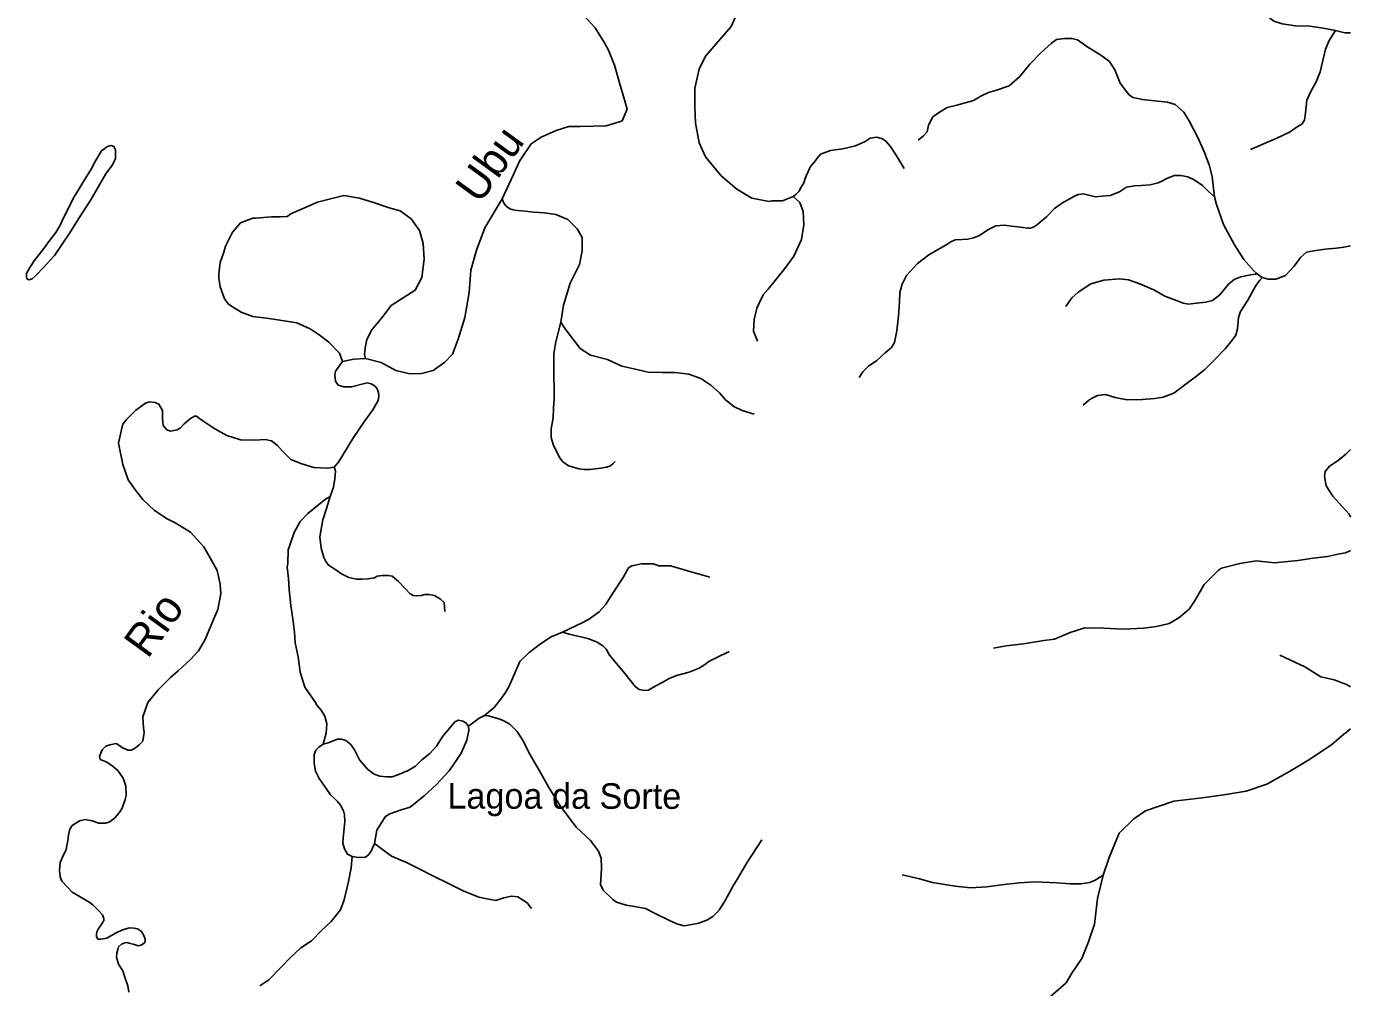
# Model space of a CAD drawing. Extents: x 436.3 to 500.4, y 8231 to 8286.4.
# Drawn here: x 491.72 to 500, y 8239.13 to 8245.15 of the extents above; entities that cross this region are included whole.
import ezdxf
from ezdxf.enums import TextEntityAlignment as Align

# ---------------------------------------------------------------- set-up
doc = ezdxf.new("R2010")
doc.units = 0
doc.header["$LTSCALE"] = 0.08
doc.linetypes.add('LONG_DASHED', pattern=[7.5, 6, -1.5])
doc.layers.add('2', color=7, linetype='Continuous', lineweight=25)
doc.layers.add('9', color=7, linetype='LONG_DASHED', lineweight=25)
doc.layers.add('61', color=7, linetype='Continuous')

msp = doc.modelspace()

# ---------------------------------------------------------------- linework, layer by layer
at = {"layer": '2'}
msp.add_lwpolyline([(492.1214, 8244.2542), (492.0745, 8244.1764), (492.0419, 8244.125), (492.0114, 8244.076), (491.9787, 8244.0059), (491.946, 8243.9452), (491.9249, 8243.9007), (491.9016, 8243.8586), (491.8643, 8243.8095), (491.8199, 8243.7486), (491.7661, 8243.6808), (491.7358, 8243.634), (491.7172, 8243.6012), (491.7172, 8243.5802), (491.7195, 8243.5684), (491.7336, 8243.5614), (491.7522, 8243.5684), (491.7756, 8243.5894), (491.8246, 8243.6385), (491.8923, 8243.7135), (491.988, 8243.8561), (492.0419, 8243.9426), (492.119, 8244.0617), (492.1681, 8244.1457), (492.2126, 8244.2251), (492.2547, 8244.2819), (492.2735, 8244.3215), (492.2736, 8244.3752), (492.2642, 8244.3963), (492.2478, 8244.4034), (492.2244, 8244.3965), (492.187, 8244.3685), (492.1472, 8244.3032)], close=True, dxfattribs=at)
for points in [[(493.574, 8240.6561), (493.6045, 8240.6636), (493.6325, 8240.6737), (493.6631, 8240.6863), (493.6886, 8240.6862), (493.714, 8240.6784), (493.7472, 8240.6528), (493.77, 8240.6196), (493.8012, 8240.558), (493.8495, 8240.4992), (493.8929, 8240.4685), (493.9285, 8240.4557), (493.9693, 8240.4504), (494.0049, 8240.4502), (494.0406, 8240.4628), (494.1043, 8240.4906), (494.1502, 8240.5184), (494.191, 8240.5564), (494.2395, 8240.5969), (494.2828, 8240.6426), (494.3211, 8240.7061), (494.367, 8240.7594), (494.3977, 8240.7949), (494.4206, 8240.805), (494.446, 8240.7998), (494.4664, 8240.7895), (494.4817, 8240.7691)], [(494.4817, 8240.7691), (494.4843, 8240.741), (494.4714, 8240.68), (494.4357, 8240.5986), (494.4076, 8240.5555), (494.3617, 8240.4895), (494.2826, 8240.4033), (494.206, 8240.3323), (494.1168, 8240.2615), (494.0601, 8240.2453), (493.9912, 8240.2202), (493.9632, 8240.2025), (493.9351, 8240.1619), (493.9096, 8240.1162), (493.8942, 8240.0341)], [(493.754, 8239.9516), (493.726, 8239.9669), (493.7057, 8240.0001), (493.6955, 8240.0357), (493.6981, 8240.0687), (493.7033, 8240.1094), (493.7084, 8240.1719), (493.706, 8240.2127), (493.7009, 8240.2381), (493.6806, 8240.2738), (493.6627, 8240.2967), (493.6373, 8240.3223), (493.6195, 8240.3377), (493.5915, 8240.3784), (493.5483, 8240.4398), (493.5254, 8240.4856), (493.5178, 8240.534), (493.5179, 8240.5901), (493.5281, 8240.6181), (493.5459, 8240.6358), (493.574, 8240.6561)], [(493.8942, 8240.0341), (493.8763, 8239.9893), (493.8584, 8239.9639), (493.838, 8239.9487), (493.7922, 8239.9464), (493.754, 8239.9516)]]:
    msp.add_lwpolyline(points, dxfattribs=at)
at = {"layer": '9'}
for points in [[(498.815, 8245.6547), (498.9221, 8245.6748), (498.9954, 8245.6637), (499.08, 8245.6161), (499.1138, 8245.5766), (499.1391, 8245.5542), (499.1391, 8245.5316), (499.1307, 8245.492), (499.1082, 8245.4412), (499.0856, 8245.4073), (499.0771, 8245.3762), (499.0884, 8245.3311), (499.1222, 8245.3087), (499.204, 8245.2863), (499.2971, 8245.2641), (499.438, 8245.2419), (499.4719, 8245.2195), (499.4944, 8245.1998), (499.5197, 8245.1802), (499.5734, 8245.1634), (499.6551, 8245.1524), (499.7453, 8245.1499), (499.8299, 8245.136), (499.906, 8245.1222)], [(496.5133, 8244.0823), (496.4978, 8244.0772), (496.4462, 8244.0565), (496.379, 8244.0566), (496.3633, 8244.0514), (496.2548, 8244.0723), (496.1619, 8244.1292), (496.0637, 8244.212), (495.9655, 8244.331), (495.9243, 8244.4189), (495.9032, 8244.5444), (495.8981, 8244.6425), (495.8983, 8244.7613), (495.9243, 8244.88), (495.9657, 8244.9625), (496.0589, 8245.0708), (496.1262, 8245.1481), (496.1624, 8245.2306), (496.1602, 8245.2649), (496.1571, 8245.3194)], [(495.2025, 8245.2173), (495.2753, 8245.1391), (495.3326, 8245.0452), (495.3586, 8244.9984), (495.395, 8244.9046), (495.4261, 8244.7952), (495.4585, 8244.6876), (495.4689, 8244.6512), (495.4742, 8244.6303), (495.4428, 8244.5576), (495.4324, 8244.5524), (495.3437, 8244.5266), (495.1821, 8244.522), (495.1091, 8244.5222), (495.0309, 8244.4965), (494.937, 8244.4553), (494.8744, 8244.4138), (494.8013, 8244.3048), (494.7647, 8244.2218), (494.6927, 8244.0679)], [(499.3735, 8244.3769), (499.4805, 8244.4229), (499.534, 8244.4457), (499.6187, 8244.4854), (499.6666, 8244.5195), (499.6948, 8244.5365), (499.7117, 8244.5619), (499.7174, 8244.6071), (499.7259, 8244.686), (499.7512, 8244.7396), (499.785, 8244.8018), (499.8104, 8244.864), (499.8274, 8244.9346), (499.8442, 8245.0051), (499.8668, 8245.0588), (499.8865, 8245.0927), (499.906, 8245.1222)], [(499.906, 8245.1222), (499.9653, 8245.1083), (500, 8245.1078)], [(497.2961, 8244.4365), (497.3284, 8244.4622), (497.351, 8244.4881), (497.3607, 8244.53), (497.3865, 8244.5815), (497.4285, 8244.6106), (497.4769, 8244.6396), (497.5381, 8244.6558), (497.5897, 8244.6688), (497.6413, 8244.685), (497.6865, 8244.7108), (497.7349, 8244.7335), (497.78, 8244.7464), (497.8638, 8244.7755), (497.9315, 8244.8337), (497.9929, 8244.9111), (498.0639, 8244.9854), (498.1283, 8245.0404), (498.1605, 8245.0663), (498.2121, 8245.0728), (498.2573, 8245.0729), (498.2926, 8245.0634), (498.3507, 8245.0216), (498.4377, 8244.967), (498.4924, 8244.9285), (498.5247, 8244.877), (498.56, 8244.7932), (498.5901, 8244.7512), (498.6127, 8244.7222), (498.6384, 8244.703), (498.6996, 8244.6903), (498.7545, 8244.684), (498.8544, 8244.6746), (498.9026, 8244.6586), (498.9575, 8244.6105), (498.9928, 8244.5525), (499.0444, 8244.4527), (499.0863, 8244.3594), (499.1153, 8244.2821), (499.1347, 8244.208), (499.1499, 8244.0818)], [(497.2074, 8244.2582), (497.1712, 8244.3202), (497.1454, 8244.3615), (497.1196, 8244.3976), (497.0937, 8244.4286), (497.0731, 8244.4441), (497.037, 8244.4544), (496.9956, 8244.4492), (496.9645, 8244.4285), (496.9032, 8244.4008), (496.8233, 8244.3815), (496.7474, 8244.3718), (496.6841, 8244.3477), (496.6678, 8244.3279), (496.6461, 8244.3008), (496.6226, 8244.2701), (496.5972, 8244.2178), (496.5881, 8244.1961), (496.5809, 8244.169), (496.5592, 8244.1347), (496.5501, 8244.1167), (496.5302, 8244.0968), (496.5133, 8244.0823)], [(496.9264, 8242.9495), (496.9486, 8242.9864), (496.9855, 8243.0209), (497.0373, 8243.0577), (497.0889, 8243.1045), (497.1283, 8243.1389), (497.1481, 8243.1685), (497.1628, 8243.2422), (497.1728, 8243.3357), (497.178, 8243.4249), (497.1804, 8243.4814), (497.1953, 8243.5356), (497.2223, 8243.5896), (497.2913, 8243.6634), (497.3626, 8243.7176), (497.4413, 8243.7643), (497.4741, 8243.7821), (497.4987, 8243.7994), (497.5258, 8243.8117), (497.57, 8243.8143), (497.6069, 8243.8167), (497.6414, 8243.8242), (497.6758, 8243.8365), (497.7348, 8243.8759), (497.7815, 8243.9006), (497.8332, 8243.9031), (497.8971, 8243.8959), (497.952, 8243.889), (497.979, 8243.8841), (497.9962, 8243.8842), (498.011, 8243.8891), (498.0331, 8243.9014), (498.0972, 8243.9556), (498.1488, 8244.0073), (498.198, 8244.0444), (498.2724, 8244.0844), (498.297, 8244.0966), (498.3289, 8244.0992), (498.3633, 8244.0919), (498.4051, 8244.0822), (498.4445, 8244.0848), (498.4961, 8244.0898), (498.5551, 8244.1121), (498.5993, 8244.1417), (498.6485, 8244.1491), (498.6903, 8244.1518), (498.7469, 8244.1568), (498.7961, 8244.1693), (498.8206, 8244.1791), (498.8501, 8244.1964), (498.8968, 8244.2138), (498.9386, 8244.2139), (498.9829, 8244.2066), (499.0221, 8244.1871), (499.0738, 8244.1529), (499.1082, 8244.1186), (499.1499, 8244.0818)], [(493.838, 8243.069), (493.8313, 8243.0949), (493.8351, 8243.1364), (493.8465, 8243.1892), (493.8767, 8243.2495), (493.941, 8243.3248), (493.9977, 8243.4001), (494.0733, 8243.4489), (494.1489, 8243.4976), (494.1905, 8243.5768), (494.2057, 8243.6901), (494.1982, 8243.7884), (494.1756, 8243.8715), (494.1227, 8243.9435), (494.0547, 8243.993), (493.9867, 8244.0121), (493.8884, 8244.0466), (493.8015, 8244.0735), (493.7033, 8244.0891), (493.6276, 8244.0706), (493.537, 8244.0484), (493.3706, 8243.9738), (493.3479, 8243.9588), (493.3064, 8243.9552), (493.2497, 8243.9555), (493.1515, 8243.9485), (493.1326, 8243.9486), (493.057, 8243.9187), (493.0079, 8243.8624), (493.0003, 8243.8473), (492.9625, 8243.7719), (492.9512, 8243.7342), (492.9285, 8243.6701), (492.921, 8243.5983), (492.921, 8243.5719), (492.9285, 8243.5189), (492.955, 8243.4431), (492.9814, 8243.4091), (493.0154, 8243.3862), (493.0607, 8243.3595), (493.1325, 8243.3327), (493.2194, 8243.321), (493.3025, 8243.3093), (493.4082, 8243.2936), (493.4913, 8243.2554), (493.548, 8243.2173), (493.6084, 8243.1717), (493.6745, 8243.103), (493.6944, 8243.0515)], [(494.6927, 8244.0679), (494.5852, 8243.8882), (494.5329, 8243.7479), (494.4963, 8243.6231), (494.4858, 8243.4824), (494.4597, 8243.3262), (494.4179, 8243.191), (494.3814, 8243.0973), (494.3344, 8243.0454), (494.2615, 8242.9936), (494.1891, 8242.9755), (494.1156, 8242.9735), (494.0282, 8242.9935), (493.9364, 8243.0446), (493.838, 8243.069)], [(495.06, 8243.2976), (495.0759, 8243.4036), (495.1186, 8243.5413), (495.177, 8243.6578), (495.193, 8243.7425), (495.1931, 8243.8273), (495.1613, 8243.8805), (495.1029, 8243.9389), (495.0292, 8243.9696), (494.958, 8243.9809), (494.8917, 8243.9861), (494.8364, 8243.9924), (494.7884, 8243.9963), (494.7626, 8244.0001), (494.7418, 8244.0063), (494.7172, 8244.0236), (494.7025, 8244.0421), (494.6927, 8244.0679)], [(496.2902, 8243.1783), (496.2644, 8243.2404), (496.2696, 8243.3127), (496.2852, 8243.3851), (496.3007, 8243.4161), (496.3267, 8243.4677), (496.3577, 8243.5038), (496.4613, 8243.6329), (496.5181, 8243.7104), (496.5647, 8243.8136), (496.5803, 8243.9067), (496.5753, 8243.9893), (496.5547, 8244.0461), (496.5133, 8244.0823)], [(499.1499, 8244.0818), (499.1609, 8244.0329), (499.2061, 8243.9073), (499.2737, 8243.7818), (499.3318, 8243.6885), (499.3962, 8243.6178), (499.4147, 8243.6005)], [(499.4489, 8243.5765), (499.4847, 8243.5666), (499.5318, 8243.5654), (499.5929, 8243.5884), (499.6477, 8243.6466), (499.6864, 8243.7016), (499.7251, 8243.7339), (499.7702, 8243.7438), (499.8412, 8243.7536), (499.9121, 8243.7604), (499.9572, 8243.7669), (500, 8243.7745)], [(498.2185, 8243.3938), (498.2572, 8243.4488), (498.2959, 8243.4843), (498.3765, 8243.5361), (498.4571, 8243.5588), (498.5539, 8243.5688), (498.6119, 8243.5624), (498.6829, 8243.5369), (498.7699, 8243.4984), (498.8376, 8243.4599), (498.9214, 8243.4279), (498.9536, 8243.4151), (498.9859, 8243.4088), (499.0375, 8243.4153), (499.0955, 8243.422), (499.1375, 8243.4318), (499.1826, 8243.4674), (499.2375, 8243.5352), (499.2729, 8243.5644), (499.3148, 8243.5806), (499.3631, 8243.5905), (499.3888, 8243.5943), (499.4066, 8243.5976), (499.4147, 8243.6005)], [(498.3279, 8242.7768), (498.3602, 8242.8059), (498.3795, 8242.8189), (498.4182, 8242.8384), (498.4666, 8242.8449), (498.5279, 8242.8258), (498.602, 8242.8099), (498.6988, 8242.8133), (498.7762, 8242.82), (498.8278, 8242.8266), (498.8955, 8242.8525), (498.9891, 8242.9237), (499.0278, 8242.9529), (499.0891, 8243.0014), (499.1471, 8243.0596), (499.2148, 8243.1307), (499.2605, 8243.1836), (499.2831, 8243.216), (499.2927, 8243.2547), (499.2992, 8243.3256), (499.3121, 8243.3644), (499.3572, 8243.4354), (499.4056, 8243.5226), (499.4204, 8243.543), (499.4337, 8243.5587), (499.4434, 8243.5702), (499.4489, 8243.5765)], [(499.4147, 8243.6005), (499.4259, 8243.59), (499.4429, 8243.5782), (499.4489, 8243.5765)], [(495.4, 8242.4243), (495.3851, 8242.4095), (495.3702, 8242.3972), (495.3455, 8242.3898), (495.3108, 8242.3825), (495.244, 8242.3753), (495.2069, 8242.3755), (495.1747, 8242.378), (495.1079, 8242.398), (495.0732, 8242.4229), (495.0534, 8242.4477), (495.0139, 8242.5247), (494.9991, 8242.5742), (494.9991, 8242.6287), (495.0116, 8242.6979), (495.014, 8242.7598), (495.0191, 8242.8143), (495.0191, 8242.8786), (495.0167, 8242.953), (495.0167, 8243.0148), (495.0168, 8243.1014), (495.0288, 8243.1742), (495.06, 8243.2976)], [(496.269, 8242.7217), (496.1947, 8242.7431), (496.1417, 8242.7697), (496.0886, 8242.8122), (496.0516, 8242.8546), (495.9986, 8242.9025), (495.935, 8242.945), (495.8607, 8242.9717), (495.7759, 8242.9825), (495.6963, 8242.9827), (495.606, 8242.983), (495.5159, 8243.0044), (495.4416, 8243.0206), (495.3515, 8243.0632), (495.2454, 8243.0901), (495.1819, 8243.1328), (495.0864, 8243.2552), (495.06, 8243.2976)], [(493.6944, 8243.0515), (493.6506, 8242.9907), (493.6454, 8242.9646), (493.6506, 8242.9281), (493.6663, 8242.9019), (493.7028, 8242.8913), (493.7496, 8242.8911), (493.8486, 8242.9167), (493.8742, 8242.9114), (493.898, 8242.8961), (493.911, 8242.8787), (493.9195, 8242.8569), (493.9217, 8242.8332), (493.9174, 8242.8072), (493.8849, 8242.7488), (493.833, 8242.6799), (493.7637, 8242.574), (493.6988, 8242.4682), (493.6685, 8242.4206), (493.6413, 8242.3893)], [(493.838, 8243.069), (493.7655, 8243.066), (493.6944, 8243.0515)], [(493.6413, 8242.3893), (493.5995, 8242.3819), (493.5157, 8242.3861), (493.4396, 8242.4093), (493.371, 8242.4363), (493.3178, 8242.4899), (493.2873, 8242.5244), (493.2492, 8242.555), (493.2111, 8242.5628), (493.1465, 8242.5592), (493.0552, 8242.5596), (492.9713, 8242.5867), (492.8953, 8242.6289), (492.8268, 8242.675), (492.7997, 8242.6941), (492.7807, 8242.7094), (492.7693, 8242.7094), (492.7427, 8242.6943), (492.7046, 8242.6601), (492.678, 8242.6335), (492.659, 8242.6221), (492.64, 8242.6184), (492.6171, 8242.6146), (492.5943, 8242.6223), (492.5715, 8242.6491), (492.5677, 8242.6911), (492.5676, 8242.7445), (492.5447, 8242.7827), (492.522, 8242.7942), (492.4877, 8242.7982), (492.4611, 8242.7906), (492.4003, 8242.7451), (492.3427, 8242.6878), (492.3198, 8242.6573), (492.3085, 8242.6154), (492.2933, 8242.5391), (492.32, 8242.4055), (492.3543, 8242.3101), (492.4, 8242.2451), (492.4456, 8242.1877), (492.5179, 8242.1188), (492.5978, 8242.0651), (492.648, 8242.0399), (492.7431, 8241.9825), (492.8268, 8241.8906), (492.8762, 8241.8028), (492.9105, 8241.7416), (492.9295, 8241.6577), (492.9333, 8241.5967), (492.9142, 8241.4977), (492.88, 8241.4216), (492.8344, 8241.3113), (492.7925, 8241.2391), (492.7431, 8241.1859), (492.667, 8241.1137), (492.6176, 8241.0719), (492.5416, 8240.9959), (492.4769, 8240.9161), (492.4457, 8240.8268), (492.4495, 8240.7582), (492.4532, 8240.7278), (492.4456, 8240.6745), (492.4228, 8240.6517), (492.4, 8240.6328), (492.3734, 8240.6175), (492.3505, 8240.6176), (492.3202, 8240.633), (492.2784, 8240.6597), (492.2394, 8240.6512), (492.2128, 8240.6437), (492.19, 8240.6208), (492.1749, 8240.579), (492.1786, 8240.5599), (492.2166, 8240.5447), (492.2507, 8240.5218), (492.2887, 8240.4913), (492.3229, 8240.4418), (492.3381, 8240.3922), (492.3418, 8240.3351), (492.3341, 8240.3086), (492.3151, 8240.2553), (492.2962, 8240.225), (492.2695, 8240.1947), (492.2466, 8240.1756), (492.2315, 8240.1681), (492.2124, 8240.1605), (492.1706, 8240.1606), (492.1289, 8240.1758), (492.0833, 8240.1835), (492.0491, 8240.1759), (492.0035, 8240.1456), (491.9883, 8240.1229), (491.9807, 8240.0886), (491.9769, 8240.0506), (491.9693, 8240.0202)], [(500, 8242.0752), (499.9916, 8242.0941), (499.9503, 8242.1415), (499.89, 8242.2079), (499.8479, 8242.2715), (499.8364, 8242.3304), (499.8424, 8242.3631), (499.8678, 8242.3949), (499.9217, 8242.43), (499.9712, 8242.4715), (500, 8242.4988)], [(493.6174, 8242.2056), (493.6387, 8242.2644), (493.6471, 8242.3169), (493.6513, 8242.3632), (493.6413, 8242.3893)], [(493.574, 8240.6561), (493.5919, 8240.7247), (493.5962, 8240.7835), (493.5836, 8240.8297), (493.5647, 8240.8613), (493.529, 8240.9056), (493.529, 8240.9098), (493.4578, 8241.013), (493.4285, 8241.1055), (493.4174, 8241.2029), (493.3986, 8241.2891), (493.3944, 8241.3564), (493.384, 8241.4405), (493.3714, 8241.5226), (493.3609, 8241.6205), (493.3568, 8241.6921), (493.3484, 8241.7635), (493.3526, 8241.7866), (493.3547, 8241.8708), (493.3631, 8241.8939), (493.3925, 8241.98), (493.4283, 8242.0487), (493.4767, 8242.099), (493.5439, 8242.1533), (493.5879, 8242.1889), (493.6174, 8242.2056)], [(494.3347, 8241.4866), (494.3292, 8241.5413), (494.3075, 8241.5632), (494.2692, 8241.5852), (494.2356, 8241.5916), (494.2083, 8241.5917), (494.1852, 8241.5855), (494.16, 8241.5835), (494.1369, 8241.5857), (494.118, 8241.5963), (494.0865, 8241.6301), (494.0445, 8241.6744), (494.0046, 8241.7061), (493.9815, 8241.7104), (493.9437, 8241.7106), (493.9101, 8241.7066), (493.8933, 8241.6961), (493.8555, 8241.69), (493.8177, 8241.688), (493.782, 8241.6882), (493.7337, 8241.6989), (493.6832, 8241.7244), (493.6518, 8241.7476), (493.6056, 8241.7751), (493.5902, 8241.799), (493.5776, 8241.8243), (493.5608, 8241.8832), (493.5524, 8241.9527), (493.5713, 8242.0598), (493.5944, 8242.1312), (493.6174, 8242.2056)], [(497.7672, 8241.2553), (497.8466, 8241.2714), (497.9546, 8241.2844), (498.0816, 8241.3037), (498.1484, 8241.3134), (498.2468, 8241.3549), (498.3389, 8241.3837), (498.4564, 8241.3809), (498.5803, 8241.375), (498.7041, 8241.3817), (498.7866, 8241.3914), (498.8661, 8241.4107), (498.9264, 8241.4457), (498.9899, 8241.4998), (499.0281, 8241.557), (499.0852, 8241.6555), (499.1741, 8241.7445), (499.1931, 8241.7573), (499.3075, 8241.7862), (499.4105, 8241.8031), (499.5248, 8241.7908), (499.6708, 8241.804), (499.7661, 8241.8201), (499.855, 8241.8299), (499.9311, 8241.846), (499.9691, 8241.8537), (499.9866, 8241.862), (500, 8241.8674)], [(495.9916, 8241.6998), (495.9344, 8241.7168), (495.8672, 8241.737), (495.7967, 8241.7574), (495.7463, 8241.7709), (495.6723, 8241.7711), (495.6387, 8241.7846), (495.5648, 8241.7847), (495.5043, 8241.7715), (495.484, 8241.7581), (495.4504, 8241.6976), (495.3898, 8241.6071), (495.3596, 8241.5601), (495.3393, 8241.5266), (495.299, 8241.483), (495.2385, 8241.4396), (495.1982, 8241.4162), (495.07, 8241.3556)], [(495.07, 8241.3556), (494.9991, 8241.3263), (494.9319, 8241.2829), (494.8612, 8241.2293), (494.8041, 8241.1725), (494.7638, 8241.0819), (494.7368, 8241.0183), (494.7133, 8240.9781), (494.683, 8240.9345), (494.6426, 8240.8843), (494.5829, 8240.8359)], [(496.1123, 8241.2348), (496.0363, 8241.197), (495.9857, 8241.1738), (495.9582, 8241.1528), (495.9244, 8241.1318), (495.8632, 8241.1066), (495.7914, 8241.0877), (495.7428, 8241.0688), (495.6943, 8241.0415), (495.6542, 8241.0205), (495.6288, 8241.0058), (495.6077, 8240.9932), (495.5803, 8240.9912), (495.5508, 8240.9976), (495.5254, 8241.0167), (495.4622, 8241.0948), (495.3653, 8241.2133), (495.3442, 8241.2492), (495.3231, 8241.2703), (495.2873, 8241.2936), (495.2282, 8241.317), (495.1671, 8241.332), (495.1122, 8241.3448), (495.07, 8241.3556)], [(499.5568, 8241.2128), (499.7152, 8241.1385), (499.8152, 8241.0779), (499.8986, 8241.0587), (499.9755, 8241.0292), (500, 8241.0152)], [(494.5829, 8240.8359), (494.5485, 8240.8176), (494.4817, 8240.7691)], [(496.3169, 8240.0576), (496.2226, 8239.9136), (496.1654, 8239.8132), (496.1384, 8239.7697), (496.0879, 8239.6761), (496.0508, 8239.616), (496.0105, 8239.5759), (495.9768, 8239.5559), (495.923, 8239.5359), (495.8793, 8239.5259), (495.8322, 8239.5193), (495.7919, 8239.5294), (495.7448, 8239.5495), (495.6508, 8239.5965), (495.5903, 8239.6268), (495.5198, 8239.6404), (495.4694, 8239.6472), (495.4089, 8239.6674), (495.3854, 8239.6842), (495.3249, 8239.7413), (495.3082, 8239.7781), (495.315, 8239.8752), (495.315, 8239.8819), (495.3117, 8239.9422), (495.2949, 8239.9857), (495.2446, 8240.0529), (495.1573, 8240.1336), (495.0554, 8240.2697), (494.985, 8240.3841), (494.9347, 8240.4748), (494.8676, 8240.5891), (494.8206, 8240.6832), (494.787, 8240.7338), (494.7401, 8240.7809), (494.6997, 8240.8046), (494.673, 8240.8147), (494.6058, 8240.8318), (494.5829, 8240.8359)], [(498.453, 8239.8364), (498.49, 8239.9457), (498.5528, 8240.0974), (498.6446, 8240.1891), (498.7181, 8240.2381), (498.8955, 8240.2997), (499.0728, 8240.3186), (499.2074, 8240.3373), (499.3482, 8240.3621), (499.4766, 8240.4053), (499.6173, 8240.485), (499.7335, 8240.5524), (499.8802, 8240.6506), (499.9585, 8240.7178), (499.9837, 8240.7361), (500, 8240.7513)], [(491.9693, 8240.0202), (491.9653, 8239.9936), (491.9501, 8239.967), (491.9273, 8239.9157), (491.9234, 8239.8663), (491.9271, 8239.8245), (491.9386, 8239.7979)], [(494.8773, 8239.6261), (494.8498, 8239.6615), (494.8262, 8239.6773), (494.7908, 8239.7009), (494.7514, 8239.7051), (494.7042, 8239.6935), (494.653, 8239.6779), (494.6098, 8239.686), (494.5468, 8239.698), (494.4485, 8239.7376), (494.3541, 8239.785), (494.2637, 8239.8286), (494.1654, 8239.8799), (494.0947, 8239.9155), (494.0003, 8239.9551), (493.8942, 8240.0341)], [(493.1773, 8239.1423), (493.2324, 8239.1813), (493.3072, 8239.2555), (493.3663, 8239.318), (493.4332, 8239.3805), (493.5001, 8239.4235), (493.5631, 8239.49), (493.6222, 8239.5446), (493.6813, 8239.6189), (493.7049, 8239.6816), (493.7327, 8239.7953), (493.7485, 8239.8816), (493.754, 8239.9516)], [(497.1944, 8239.8378), (497.3045, 8239.8136), (497.3841, 8239.7895), (497.5273, 8239.7657), (497.6227, 8239.7561), (497.7248, 8239.763), (497.8335, 8239.7765), (497.9291, 8239.7865), (498.0246, 8239.7934), (498.163, 8239.7872), (498.2453, 8239.781), (498.3128, 8239.7823), (498.3695, 8239.7906), (498.4019, 8239.8041), (498.4297, 8239.8203), (498.453, 8239.8364)], [(498.1229, 8239.0767), (498.2208, 8239.1621), (498.2576, 8239.2231), (498.3189, 8239.3145), (498.3616, 8239.4181), (498.3984, 8239.5278), (498.4171, 8239.6887), (498.453, 8239.8364)], [(491.9386, 8239.7979), (492.003, 8239.7294), (492.1131, 8239.6647), (492.132, 8239.6495), (492.1683, 8239.6145), (492.1934, 8239.5864), (492.2008, 8239.5642), (492.2008, 8239.5509), (492.1889, 8239.5316), (492.1652, 8239.4977), (492.1563, 8239.4799), (492.1547, 8239.4665), (492.1547, 8239.4503), (492.1636, 8239.4355), (492.1828, 8239.434), (492.2198, 8239.4413), (492.2732, 8239.4724), (492.3132, 8239.4915), (492.3592, 8239.5062), (492.3903, 8239.5047), (492.4109, 8239.4988), (492.4361, 8239.4824), (492.4509, 8239.4572), (492.4597, 8239.435), (492.4597, 8239.4188), (492.4508, 8239.4069), (492.433, 8239.3966), (492.4167, 8239.3937), (492.3841, 8239.4041), (492.3649, 8239.4086), (492.3471, 8239.4131), (492.3323, 8239.4116), (492.3116, 8239.4043), (492.2937, 8239.3879), (492.2878, 8239.3702), (492.2819, 8239.348), (492.2804, 8239.3229), (492.2935, 8239.2785), (492.3194, 8239.2369), (492.332, 8239.1968), (492.3509, 8239.142), (492.3572, 8239.1041)]]:
    msp.add_lwpolyline(points, dxfattribs=at)

# ---------------------------------------------------------------- texts
at = {"layer": '61'}
msp.add_text('Rio                                          Ubu', height=0.2, rotation=53.913, dxfattribs=at).set_placement((493.6575, 8242.8059), align=Align.CENTER)
msp.add_text('Lagoa da Sorte', height=0.16, rotation=359.932, dxfattribs=at).set_placement((494.3502, 8240.252))

doc.saveas('drawing.dxf')
